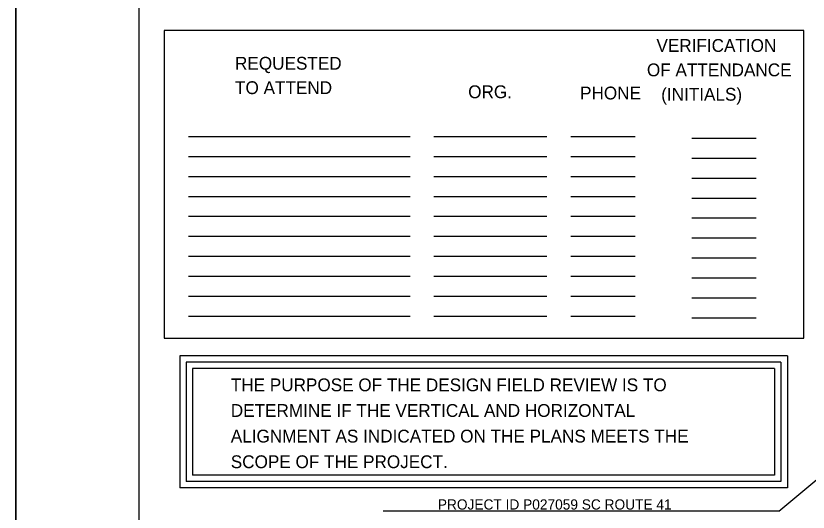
# Model space of a CAD drawing. Extents: x -12279 to -10482, y 3228 to 4378.
# Drawn here: x -12278 to -11660, y 3549 to 3937 of the extents above; entities that cross this region are included whole.
import ezdxf

# ---------------------------------------------------------------- set-up
doc = ezdxf.new("R2010")
doc.units = 0
for name, color, linetype in [('RD_SHT_Bndy', 7, 'Continuous'), ('RD_SHT_IplotShp', 7, 'Continuous'), ('RD_SHT_Snap', 7, 'Continuous'), ('RD_SHT_TX', 7, 'Continuous')]:
    doc.layers.add(name, color=color, linetype=linetype)

msp = doc.modelspace()

# ---------------------------------------------------------------- linework, layer by layer
at = {"layer": 'RD_SHT_Bndy'}
for p, q in [((-12182.24, 4327.98), (-12182.24, 3277.18)), ((-12143.35, 3842.73), (-11970.5, 3842.73)), ((-11951.83, 3842.73), (-11863.67, 3842.73)), ((-11845, 3842.73), (-11794.62, 3842.73)), ((-11750.63, 3841.43), (-11700.26, 3841.43)), ((-12143.35, 3827.13), (-11970.5, 3827.13)), ((-11951.83, 3827.13), (-11863.67, 3827.13)), ((-11845, 3827.13), (-11794.62, 3827.13)), ((-11750.63, 3825.83), (-11700.26, 3825.83)), ((-12143.35, 3811.53), (-11970.5, 3811.53)), ((-11951.83, 3811.53), (-11863.67, 3811.53)), ((-11845, 3811.53), (-11794.62, 3811.53)), ((-11750.63, 3810.23), (-11700.26, 3810.23)), ((-12143.35, 3795.93), (-11970.5, 3795.93)), ((-11951.83, 3795.93), (-11863.67, 3795.93)), ((-11845, 3795.93), (-11794.62, 3795.93)), ((-11750.63, 3794.63), (-11700.26, 3794.63)), ((-12143.35, 3780.33), (-11970.5, 3780.33)), ((-11951.83, 3780.33), (-11863.67, 3780.33)), ((-11845, 3780.33), (-11794.62, 3780.33)), ((-11750.63, 3779.03), (-11700.26, 3779.03)), ((-12143.35, 3764.73), (-11970.5, 3764.73)), ((-11951.83, 3764.73), (-11863.67, 3764.73)), ((-11845, 3764.73), (-11794.62, 3764.73)), ((-11750.63, 3763.43), (-11700.26, 3763.43)), ((-12143.35, 3749.13), (-11970.5, 3749.13)), ((-11951.83, 3749.13), (-11863.67, 3749.13)), ((-11845, 3749.13), (-11794.62, 3749.13)), ((-11750.63, 3747.83), (-11700.26, 3747.83)), ((-12143.35, 3733.53), (-11970.5, 3733.53)), ((-11951.83, 3733.53), (-11863.67, 3733.53)), ((-11845, 3733.53), (-11794.62, 3733.53)), ((-11750.63, 3732.23), (-11700.26, 3732.23)), ((-12143.35, 3717.93), (-11970.5, 3717.93)), ((-11951.83, 3717.93), (-11863.67, 3717.93)), ((-11845, 3717.93), (-11794.62, 3717.93)), ((-11750.63, 3716.63), (-11700.26, 3716.63)), ((-12143.35, 3702.33), (-11970.5, 3702.33)), ((-11951.83, 3702.33), (-11863.67, 3702.33)), ((-11845, 3702.33), (-11794.62, 3702.33)), ((-11750.63, 3701.03), (-11700.26, 3701.03)), ((-12150.32, 3671.5), (-12150.32, 3568.34)), ((-11675.94, 3671.5), (-12150.32, 3671.5)), ((-11675.94, 3671.5), (-11675.94, 3568.34)), ((-11680.94, 3666.5), (-12145.32, 3666.5)), ((-12145.32, 3666.5), (-12145.32, 3573.34)), ((-11680.94, 3666.5), (-11680.94, 3573.34)), ((-11685.94, 3661.5), (-12140.32, 3661.5)), ((-12140.32, 3661.5), (-12140.32, 3578.34)), ((-11685.94, 3661.5), (-11685.94, 3578.34)), ((-11685.94, 3578.34), (-12140.32, 3578.34)), ((-11680.94, 3573.34), (-12145.32, 3573.34)), ((-11675.94, 3568.34), (-12150.32, 3568.34))]:
    msp.add_line(p, q, dxfattribs=at)
msp.add_lwpolyline([(-12162.35, 3925.31), (-12162.35, 3685.32), (-11662.99, 3685.32), (-11662.99, 3925.31)], close=True, dxfattribs=at)
at = {"layer": 'RD_SHT_IplotShp'}
msp.add_lwpolyline([(-12278.24, 4352.98), (-10482.25, 4352.98), (-10482.25, 3252.98), (-12278.24, 3252.98)], close=True, dxfattribs=at)
at = {"layer": 'RD_SHT_Snap'}
msp.add_line((-12278.24, 4352.98), (-12278.24, 3252.98), dxfattribs=at)
at = {"layer": 'RD_SHT_TX'}
for q in [(-11315.35, 3856.67), (-11991.36, 3550.14)]:
    msp.add_line((-11682.6, 3550.14), q, dxfattribs=at)

# ---------------------------------------------------------------- texts
for s, height, p in [('  VERIFICATION ', 10.0001, (-11785.57, 3908.69)), ('  REQUESTED  ', 10.0001, (-12114.55, 3894.79)), ('OF ATTENDANCE', 10.0001, (-11785.57, 3889.64)), ('  TO ATTEND', 10.0001, (-12114.55, 3875.74)), ('ORG.', 10, (-11925.1, 3872.54)), ('PHONE', 10, (-11837.76, 3871.57)), ('   (INITIALS)', 10.0001, (-11785.57, 3870.59)), ('THE PURPOSE OF THE DESIGN FIELD REVIEW IS TO', 10.0001, (-12110.44, 3643.79)), ('DETERMINE IF THE VERTICAL AND HORIZONTAL', 10.0001, (-12110.44, 3623.79)), ('ALIGNMENT AS INDICATED ON THE PLANS MEETS THE', 10.0001, (-12110.44, 3603.79)), ('SCOPE OF THE PROJECT.', 10.0001, (-12110.44, 3583.79)), ('PROJECT ID P027059 SC ROUTE 41', 8, (-11948.8, 3551.44))]:
    msp.add_text(s, height=height, dxfattribs=at).set_placement(p)

doc.saveas('drawing.dxf')
